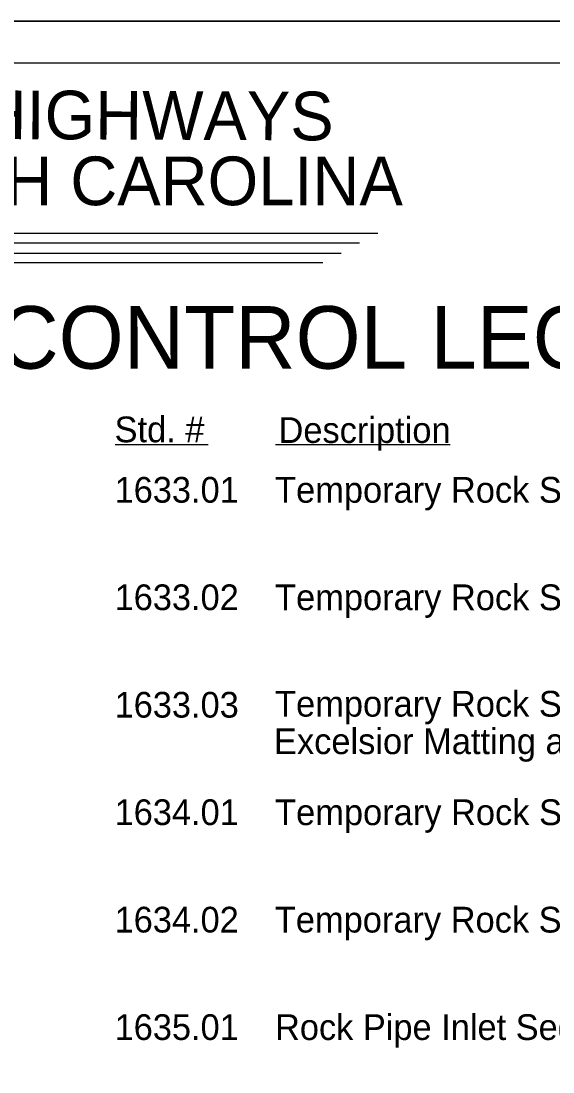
# Model space of a CAD drawing. Extents: x 1677124 to 1678808, y 1331209 to 1332299.
# Drawn here: x 1677966 to 1678246, y 1331745 to 1332299 of the extents above; entities that cross this region are included whole.
import ezdxf

# ---------------------------------------------------------------- set-up
doc = ezdxf.new("R2010")
doc.units = 0
for name, color, linetype in [('EC Title Sheet CELL', 7, 'Continuous'), ('Old_Level_1', 7, 'Continuous'), ('Old_Level_12', 7, 'Continuous'), ('Sheet Plan CELL', 7, 'Continuous'), ('Sheet Plot Border Outside CELL', 7, 'Continuous'), ('z - Construction', 7, 'Continuous')]:
    doc.layers.add(name, color=color, linetype=linetype)

msp = doc.modelspace()

# ---------------------------------------------------------------- linework, layer by layer
at = {"layer": 'EC Title Sheet CELL'}
for p, q in [((1678015.41, 1332075.4), (1678064.44, 1332075.45)), ((1678100.01, 1332075.4), (1678192.12, 1332075.4))]:
    msp.add_line(p, q, dxfattribs=at)
at = {"layer": 'Old_Level_1'}
for p, q in [((1677732.72, 1332186.84), (1678153.9, 1332186.84)), ((1677741.94, 1332181.69), (1678144.26, 1332181.69)), ((1677751.17, 1332176.25), (1678134.62, 1332176.25)), ((1677760.8, 1332171.37), (1678124.98, 1332171.37))]:
    msp.add_line(p, q, dxfattribs=at)
at = {"layer": 'Sheet Plan CELL'}
msp.add_line((1678794.2, 1332276.27), (1677160.26, 1332276.27), dxfattribs=at)
at = {"layer": 'Sheet Plot Border Outside CELL'}
msp.add_lwpolyline([(1677124.14, 1332298.56), (1678807.57, 1332298.56), (1678807.57, 1331209.28), (1677124.14, 1331209.28)], close=True, dxfattribs=at)
at = {"layer": 'z - Construction'}
msp.add_line((1678807.57, 1332298.56), (1677124.14, 1332298.56), dxfattribs=at)

# ---------------------------------------------------------------- texts
at = {"layer": 'EC Title Sheet CELL'}
for s, height, p in [('Std. #', 13.565, (1678015.18, 1332076.6)), ('Description', 13.5651, (1678101.6, 1332076.25)), ('1633.01', 13.548, (1678015.18, 1332044.78)), ('Temporary Rock Silt Check Type A', 13.5651, (1678099.78, 1332044.76)), ('1633.02', 13.548, (1678015.18, 1331988.16)), ('Temporary Rock Silt Check Type B', 13.5651, (1678099.78, 1331988.14)), ('1633.03', 13.548, (1678015.18, 1331931.54)), ('Temporary Rock Silt Check Type A with', 13.5651, (1678099.78, 1331932.05)), ('Excelsior Matting and Flocculant', 13.5651, (1678099.23, 1331912.3)), ('1634.01', 13.548, (1678015.18, 1331874.92)), ('Temporary Rock Sediment Dam Type A', 13.5705, (1678099.78, 1331874.9)), ('1634.02', 13.548, (1678015.18, 1331818.31)), ('Temporary Rock Sediment Dam Type B', 13.5651, (1678099.65, 1331818.29)), ('1635.01', 13.548, (1678015.18, 1331761.69)), ('Rock Pipe Inlet Sediment Trap Type A', 13.5461, (1678099.78, 1331761.69))]:
    msp.add_text(s, height=height, dxfattribs=at).set_placement(p)
at = {"layer": 'Old_Level_1'}
for s, height, p in [('STATE OF NORTH CAROLINA', 25.6387, (1677683.29, 1332201.51)), ('EROSION & SEDIMENT CONTROL LEGEND', 32.964, (1677456.68, 1332115.38))]:
    msp.add_text(s, height=height, rotation=360, dxfattribs=at).set_placement(p)
at = {"layer": 'Old_Level_12'}
msp.add_text(' DIVISION OF HIGHWAYS', height=25.6386, rotation=359.7699, dxfattribs=at).set_placement((1677717.27, 1332237.3))

doc.saveas('drawing.dxf')
